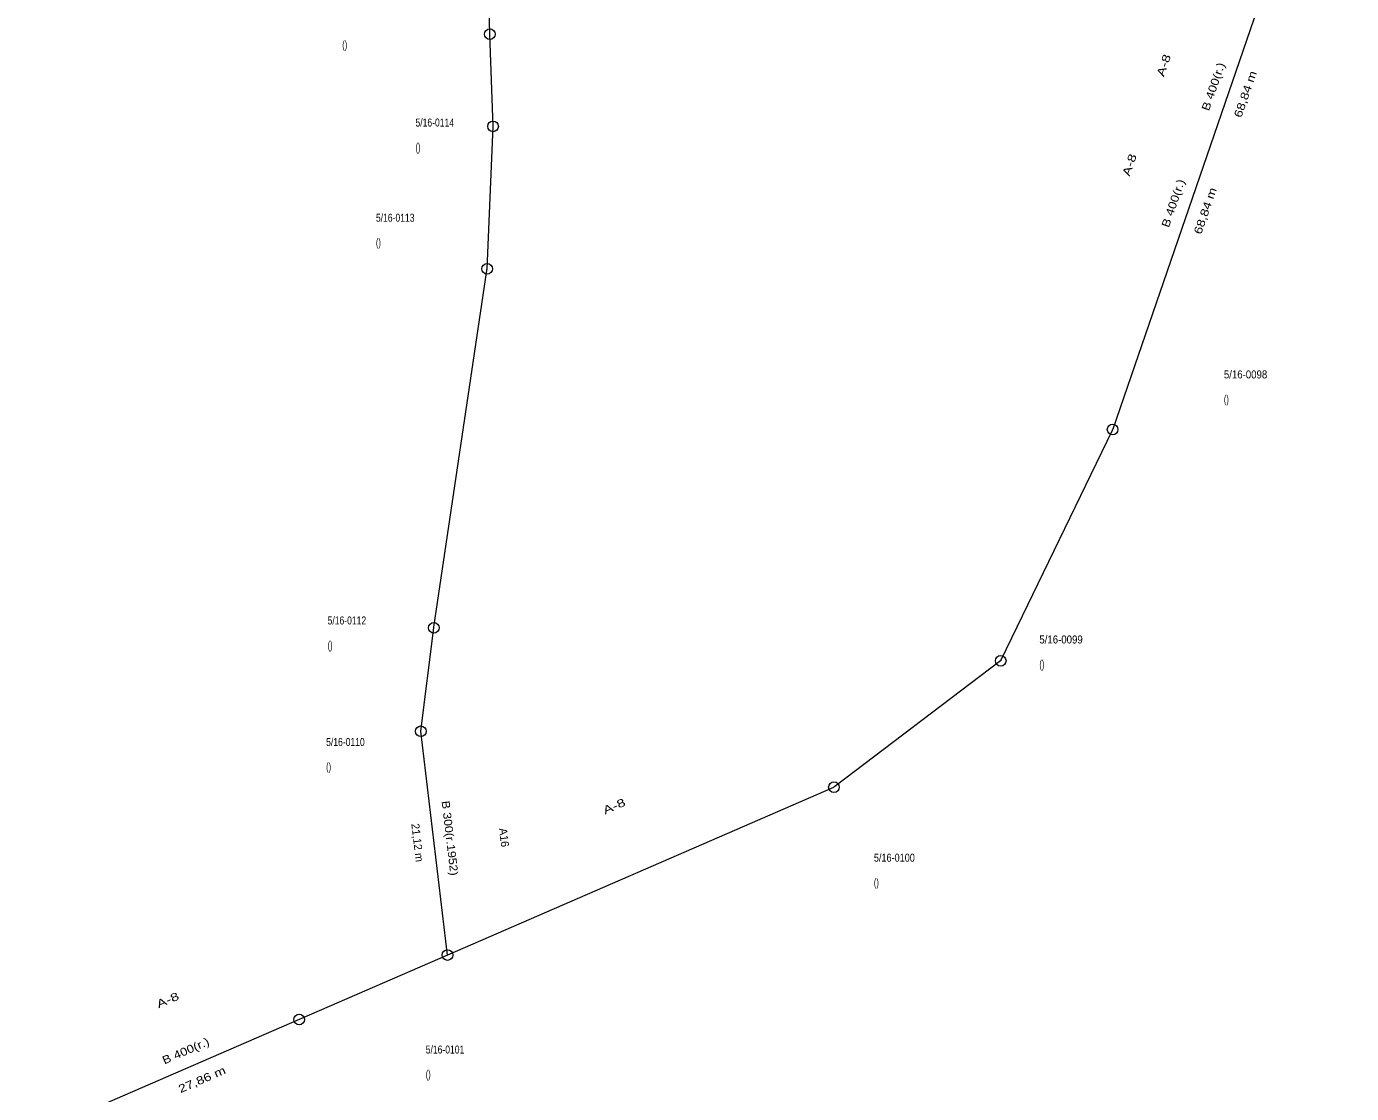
# Model space of a CAD drawing. Extents: x -710854 to -709799, y -1117012 to -1115891.
# Drawn here: x -710211.3 to -710087.2, y -1116298.3 to -1116198.3 of the extents above; entities that cross this region are included whole.
import ezdxf
from ezdxf.enums import TextEntityAlignment as Align

# ---------------------------------------------------------------- set-up
doc = ezdxf.new("R2010")
doc.units = 0
doc.header["$LTSCALE"] = 0.3
doc.layers.add('38', color=7, linetype='Continuous', lineweight=13)
doc.layers.add('44', color=7, linetype='Continuous', lineweight=13)
doc.layers.add('48', color=7, linetype='Continuous')

msp = doc.modelspace()

# ---------------------------------------------------------------- linework, layer by layer
at = {"layer": '38'}
for points in [[(-710087.18, -1116170.98), (-710109.55, -1116236.05), (-710109.565, -1116236.081)], [(-710167.93, -1116199.034), (-710167.931, -1116198.992), (-710168.42, -1116180.213)], [(-710173.174, -1116254.667), (-710173.165, -1116254.598), (-710168.204, -1116221.173), (-710168.196, -1116221.115), (-710168.182, -1116221.023), (-710168.182, -1116221.022), (-710167.63, -1116207.67), (-710167.93, -1116199.034)], [(-710109.565, -1116236.081), (-710109.605, -1116236.164), (-710120.029, -1116257.707), (-710120.055, -1116257.76)], [(-710171.9, -1116285.33), (-710174.4, -1116264.36), (-710173.174, -1116254.667)], [(-710120.055, -1116257.76), (-710120.06, -1116257.77), (-710135.59, -1116269.529), (-710135.677, -1116269.595)], [(-710135.677, -1116269.595), (-710135.71, -1116269.62), (-710171.9, -1116285.33)], [(-710171.9, -1116285.33), (-710185.577, -1116291.268), (-710185.72, -1116291.33), (-710185.798, -1116291.364), (-710211.348, -1116302.459)]]:
    msp.add_lwpolyline(points, dxfattribs=at)
at = {"layer": '44'}
for centre in [(-710167.93, -1116199.034), (-710167.63, -1116207.67), (-710168.182, -1116221.022), (-710109.565, -1116236.081), (-710173.174, -1116254.667), (-710120.055, -1116257.76), (-710174.4, -1116264.36), (-710135.677, -1116269.595), (-710171.9, -1116285.33), (-710185.798, -1116291.364)]:
    msp.add_circle(centre, 0.5, dxfattribs=at)

# ---------------------------------------------------------------- texts
at = {"layer": '48'}
for s, width, p in [('()', 0.7, (-710181.758, -1116200.39)), ('5/16-0114', 0.8, (-710174.896, -1116207.687)), ('()', 0.7, (-710174.896, -1116209.997)), ('5/16-0113', 0.8, (-710178.601, -1116216.607)), ('()', 0.7, (-710178.601, -1116218.917)), ('5/16-0098', 0.9, (-710099.14, -1116231.292)), ('()', 0.7, (-710099.14, -1116233.602)), ('5/16-0112', 0.8, (-710183.13, -1116254.348)), ('5/16-0099', 0.9, (-710116.432, -1116256.132)), ('()', 0.7, (-710183.13, -1116256.658)), ('()', 0.7, (-710116.432, -1116258.442)), ('5/16-0110', 0.8, (-710183.268, -1116265.739)), ('()', 0.7, (-710183.268, -1116268.049)), ('5/16-0100', 0.85, (-710131.94, -1116276.581)), ('()', 0.7, (-710131.94, -1116278.891)), ('5/16-0101', 0.8, (-710173.935, -1116294.559)), ('()', 0.7, (-710173.935, -1116296.869))]:
    msp.add_text(s, height=0.75, dxfattribs=dict(at, width=width)).set_placement(p)
for s, rotation, width, p in [('A-8', 71.03, 1.35, (-710104.4256, -1116202.0729)), ('B 400(r.)', 71.03, 1.2, (-710099.7814, -1116204.0644)), ('68,84 m', 71.03, 1.25, (-710096.7773, -1116204.7754)), ('A-8', 71.03, 1.35, (-710107.6336, -1116211.4049)), ('B 400(r.)', 71.03, 1.2, (-710103.5394, -1116214.9954)), ('68,84 m', 71.03, 1.25, (-710100.5353, -1116215.7064)), ('B 300(r.1952)', 276.8, 1.15, (-710172.0323, -1116274.4196)), ('A-8', 23.47, 1.4, (-710156.1319, -1116271.7264)), ('A-8', 23.47, 1.4, (-710197.9659, -1116289.8884)), ('B 400(r.)', 23.47, 1.2, (-710196.2774, -1116294.6504)), ('27,86 m', 23.47, 1.3, (-710194.7549, -1116297.3354))]:
    msp.add_text(s, height=0.75, rotation=rotation, dxfattribs=dict(at, width=width)).set_placement(p, align=Align.CENTER)
for s, p in [('21,12 m', (-710175.0748, -1116274.8386)), ('A16', (-710166.9644, -1116274.3591))]:
    msp.add_text(s, height=0.75, rotation=276.8, dxfattribs=at).set_placement(p, align=Align.CENTER)

doc.saveas('drawing.dxf')
